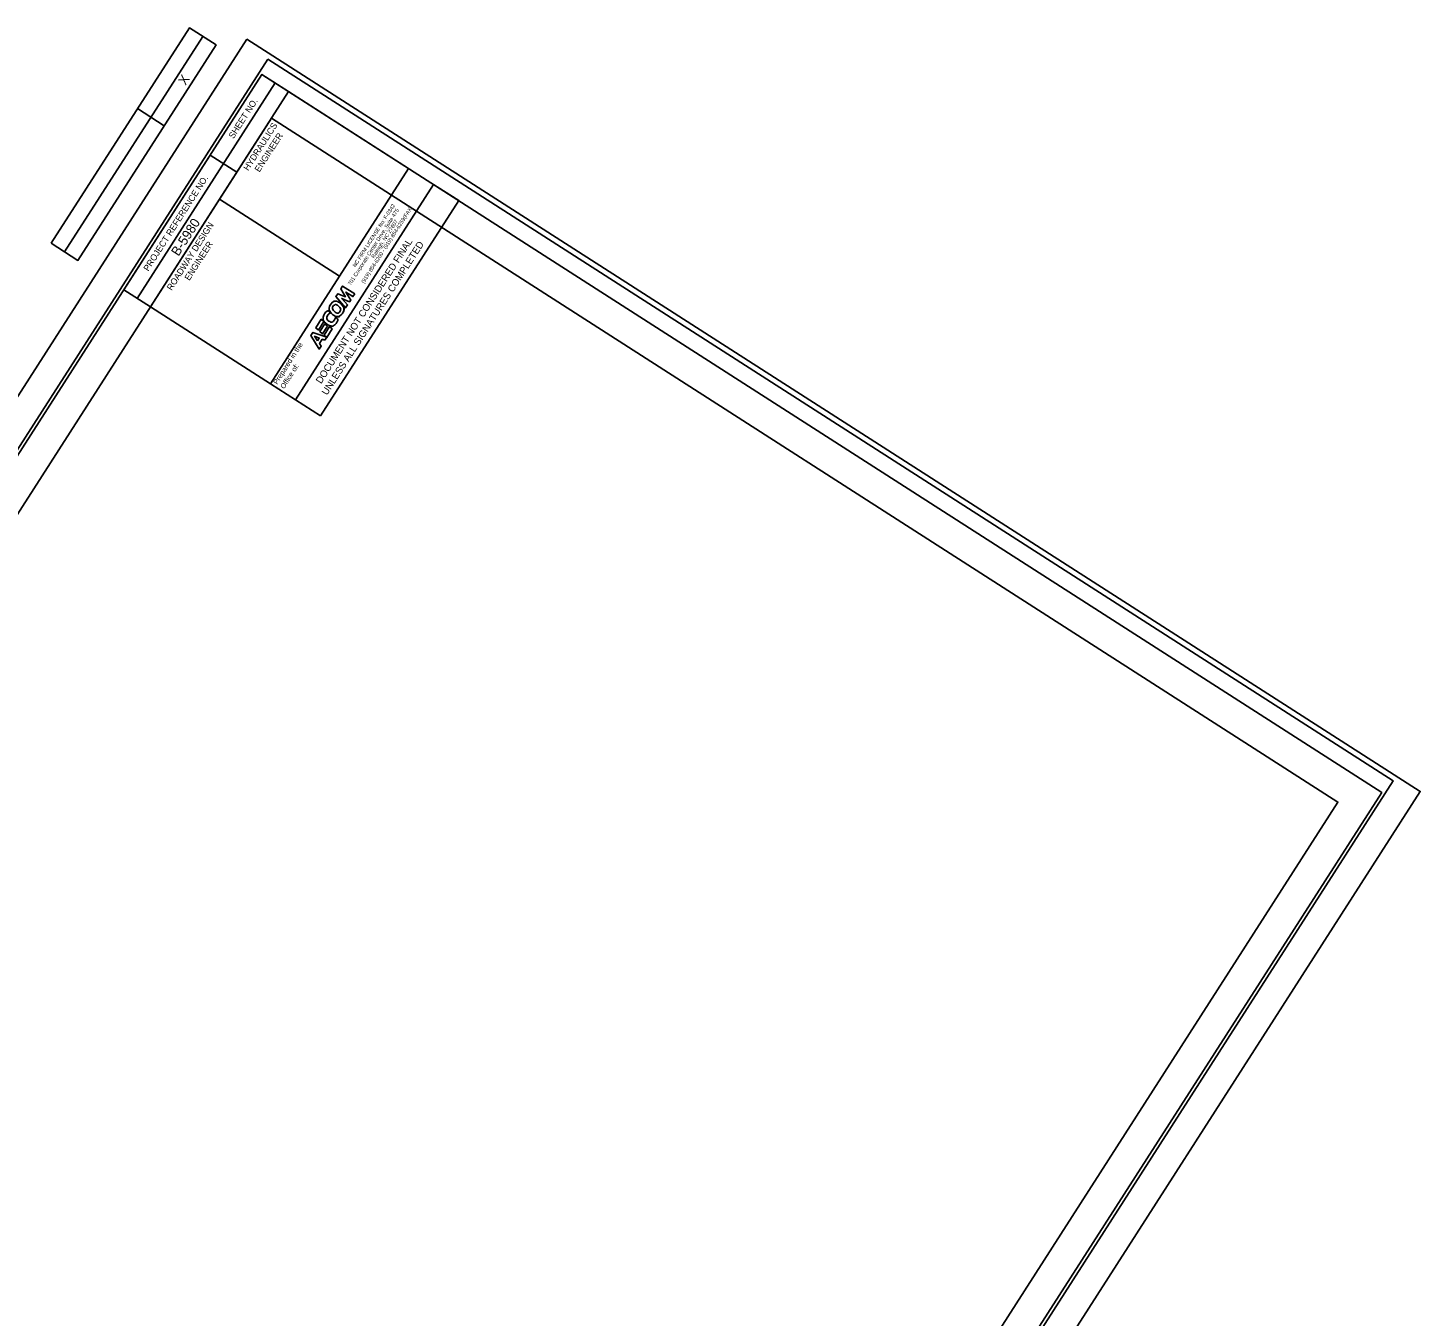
# Model space of a CAD drawing. Extents: x 2346017 to 2347860, y 841329 to 843363.
# Drawn here: x 2346762 to 2347860, y 842346 to 843363 of the extents above; entities that cross this region are included whole.
import ezdxf

# ---------------------------------------------------------------- set-up
doc = ezdxf.new("R2010")
doc.units = 0
for name, color, linetype in [('Default', 7, 'Continuous'), ('Old_Level_49', 7, 'Continuous'), ('Scratch_Level_0', 7, 'Continuous'), ('Sheet Border Standard 30in CELL', 7, 'Continuous'), ('Sheet Data Field CELL', 7, 'Continuous'), ('Sheet Plot Border Inside CELL', 7, 'Continuous'), ('Sheet Plot Border Outside CELL', 7, 'Continuous'), ('Sheet Profile CELL', 7, 'Continuous'), ('Sheet Sticker Exception Certification CELL', 7, 'Continuous')]:
    doc.layers.add(name, color=color, linetype=linetype)

# ---------------------------------------------------------------- blocks, each defined once
blk = doc.blocks.new('block 2')
at = {"layer": 'Default'}
for p, q in [((0.1023, 0.0938), (0.102, 0.0913)), ((0.102, 0.0913), (0.1093, 0.0913)), ((0.1097, 0.0938), (0.1023, 0.0938)), ((0.1093, 0.0913), (0.1097, 0.0938)), ((0.1011, 0.0858), (0.1008, 0.0833)), ((0.1008, 0.0833), (0.1081, 0.0833)), ((0.1085, 0.0858), (0.1011, 0.0858)), ((0.1014, 0.0873), (0.1017, 0.0898)), ((0.1078, 0.0873), (0.1014, 0.0873)), ((0.1017, 0.0898), (0.1082, 0.0898)), ((0.1082, 0.0898), (0.1078, 0.0873)), ((0.1081, 0.0833), (0.1085, 0.0858))]:
    blk.add_line(p, q, dxfattribs=at)
for points in [[(0.1093, 0.0913), (0.102, 0.0913), (0.1023, 0.0938), (0.1097, 0.0938), (0.1093, 0.0913)], [(0.1085, 0.0858), (0.1011, 0.0858), (0.1008, 0.0833), (0.1081, 0.0833), (0.1085, 0.0858)], [(0.1078, 0.0873), (0.1014, 0.0873), (0.1017, 0.0898), (0.1082, 0.0898), (0.1078, 0.0873)]]:
    blk.add_lwpolyline(points, dxfattribs=at)
blk = doc.blocks.new('block 3')
at = {"layer": 'Default'}
blk.add_open_spline([(0.1228, 0.0939), (0.1255, 0.0937), (0.1273, 0.0915), (0.127, 0.0884), (0.1266, 0.0853), (0.1241, 0.083), (0.1213, 0.0832), (0.1185, 0.0834), (0.1168, 0.0856), (0.1171, 0.0887), (0.1174, 0.0918), (0.1199, 0.0941), (0.1228, 0.0939)], degree=3, dxfattribs=at)

msp = doc.modelspace()

# ---------------------------------------------------------------- linework, layer by layer
at = {"layer": 'Old_Level_49'}
for p, q in [((2347006.1, 843153.2), (2347004.7, 843151)), ((2347012.2, 843150.8), (2347006.1, 843153.2)), ((2347009.9, 843159.2), (2347008.6, 843157)), ((2347008.6, 843157), (2347012.2, 843150.8)), ((2347019.6, 843153.2), (2347009.9, 843159.2)), ((2347016.3, 843148.1), (2347012.5, 843154.5)), ((2347012.5, 843154.5), (2347018.1, 843150.9)), ((2347018.1, 843150.9), (2347019.6, 843153.2)), ((2347004.7, 843151), (2347012.3, 843142)), ((2347013.9, 843144.3), (2347009.3, 843149.5)), ((2347009.3, 843149.5), (2347015.5, 843146.9)), ((2347012.3, 843142), (2347013.9, 843144.3)), ((2347015.5, 843146.9), (2347016.3, 843148.1)), ((2346986.5, 843122.7), (2346984.9, 843120.1)), ((2346984.9, 843120.1), (2346991.5, 843109.5)), ((2346997.5, 843118.8), (2346986.5, 843122.7)), ((2346990.2, 843116.1), (2346987.8, 843119.6)), ((2346987.8, 843119.6), (2346987.8, 843119.6)), ((2346987.8, 843119.6), (2346991.5, 843118.2)), ((2346991.5, 843118.2), (2346990.2, 843116.1)), ((2346991.5, 843109.5), (2346993.1, 843111.9)), ((2346991.7, 843113.9), (2346993.9, 843117.3)), ((2346993.1, 843111.9), (2346991.7, 843113.9)), ((2346993.9, 843117.3), (2346996, 843116.5)), ((2346996, 843116.5), (2346997.5, 843118.8))]:
    msp.add_line(p, q, dxfattribs=at)
for points in [[(2347019.6, 843153.2), (2347009.9, 843159.2), (2347008.6, 843157), (2347012.2, 843150.8), (2347006.1, 843153.2), (2347004.7, 843151), (2347012.3, 843142), (2347013.9, 843144.3), (2347009.3, 843149.5), (2347015.5, 843146.9), (2347016.3, 843148.1), (2347012.5, 843154.5), (2347018.1, 843150.9), (2347019.6, 843153.2)], [(2346996, 843116.5), (2346997.5, 843118.8), (2346986.5, 843122.7), (2346984.9, 843120.1), (2346991.5, 843109.5), (2346993.1, 843111.9), (2346991.7, 843113.9), (2346993.9, 843117.3), (2346996, 843116.5)], [(2346990.2, 843116.1), (2346987.8, 843119.6), (2346987.8, 843119.6), (2346991.5, 843118.2), (2346990.2, 843116.1)]]:
    msp.add_lwpolyline(points, dxfattribs=at)
for points in [[(2347008.8, 843136.5), (2347007, 843134.9), (2347004.4, 843135), (2347002.1, 843136.8), (2346999.5, 843138.9), (2346998.8, 843142.6), (2347000.7, 843145)], [(2347000.7, 843145), (2347002.5, 843147.5), (2347005.6, 843147.7), (2347008.1, 843145.7), (2347010.8, 843143.5), (2347011.4, 843139.9), (2347009.6, 843137.4), (2347009.4, 843137.1), (2347009.1, 843136.8), (2347008.8, 843136.5)], [(2347006.9, 843143.2), (2347005.5, 843144.6), (2347003.9, 843144.8), (2347002.9, 843143.8), (2347001.7, 843142.6), (2347002, 843140.7), (2347003.4, 843139.3), (2347004.8, 843137.9), (2347006.5, 843137.7), (2347007.5, 843138.7), (2347008.6, 843139.9), (2347008.4, 843141.8), (2347006.9, 843143.2)], [(2347006.9, 843143.2), (2347005.5, 843144.6), (2347003.9, 843144.8), (2347002.9, 843143.8), (2347001.7, 843142.6), (2347002, 843140.7), (2347003.4, 843139.3), (2347004.8, 843137.9), (2347006.5, 843137.7), (2347007.5, 843138.7), (2347008.6, 843139.9), (2347008.4, 843141.8), (2347006.9, 843143.2)], [(2347004.2, 843134.7), (2347004.1, 843133.9), (2347003.6, 843132.9), (2347003.3, 843132.4), (2347002.3, 843130.9), (2347000.6, 843130.6), (2346999.1, 843131.6), (2346997.6, 843132.7), (2346997.2, 843134.7), (2346998.3, 843136.3), (2346998.8, 843137.1), (2346999.5, 843137.6), (2347000.4, 843137.9), (2347000.4, 843137.9), (2346998.4, 843139.8), (2346998.4, 843139.8), (2346997.2, 843139.2), (2346996.5, 843138.6), (2346995.9, 843137.6), (2346994.1, 843134.9), (2346994.9, 843131.1), (2346997.7, 843129.2), (2347000.5, 843127.3), (2347003.6, 843127.9), (2347005.3, 843130.6), (2347005.6, 843131), (2347006.2, 843132.1), (2347006.3, 843132.9), (2347006.3, 843132.9), (2347004.2, 843134.7), (2347004.2, 843134.7)], [(2347004.2, 843134.7), (2347004.1, 843133.9), (2347003.6, 843132.9), (2347003.3, 843132.4), (2347002.3, 843130.9), (2347000.6, 843130.6), (2346999.1, 843131.6), (2346997.6, 843132.7), (2346997.2, 843134.7), (2346998.3, 843136.3), (2346998.8, 843137.1), (2346999.5, 843137.6), (2347000.4, 843137.9), (2347000.4, 843137.9), (2346998.4, 843139.8), (2346998.4, 843139.8), (2346997.2, 843139.2), (2346996.5, 843138.6), (2346995.9, 843137.6), (2346994.1, 843134.9), (2346994.9, 843131.1), (2346997.7, 843129.2), (2347000.5, 843127.3), (2347003.6, 843127.9), (2347005.3, 843130.6), (2347005.6, 843131), (2347006.2, 843132.1), (2347006.3, 843132.9), (2347006.3, 843132.9), (2347004.2, 843134.7), (2347004.2, 843134.7)]]:
    msp.add_open_spline(points, degree=3, dxfattribs=at)
at = {"layer": 'Scratch_Level_0'}
msp.add_lwpolyline([(2346953.8, 843291.8), (2346163.3, 842059.1), (2347005, 841519.3), (2347795.5, 842752)], close=True, dxfattribs=at)
at = {"layer": 'Sheet Border Standard 30in CELL'}
for p, q in [((2346790.5, 843186.2), (2346899.5, 843356.3)), ((2346801, 843179.5), (2346910.1, 843349.5)), ((2346847.8, 843149.5), (2346956.8, 843319.6)), ((2346858.3, 843142.8), (2346967.3, 843312.8)), ((2346858.3, 843142.8), (2346967.3, 843312.8)), ((2346848.1, 843299.3), (2346869.2, 843285.8)), ((2346905.4, 843262.6), (2346926.4, 843249.1)), ((2346912.8, 843227.8), (2347007.5, 843167.1))]:
    msp.add_line(p, q, dxfattribs=at)
for points in [[(2346780, 843193), (2346889, 843363), (2346910.1, 843349.5), (2346801, 843179.5)], [(2346946.2, 843326.3), (2346128.7, 842051.6), (2347012.6, 841484.8), (2347830.1, 842759.5)], [(2346837.2, 843156.3), (2346946.2, 843326.3), (2346967.3, 843312.8), (2346858.3, 843142.8)], [(2346912.8, 843227.8), (2346967.3, 843312.8), (2347062, 843252.1), (2347007.5, 843167.1)], [(2346858.3, 843142.8), (2346912.8, 843227.8), (2347007.5, 843167.1), (2346953, 843082.1)]]:
    msp.add_lwpolyline(points, close=True, dxfattribs=at)
at = {"layer": 'Sheet Plot Border Inside CELL'}
msp.add_lwpolyline([(2346950.9, 843338.3), (2346042.7, 841922.1), (2346930.8, 841352.5), (2347839, 842768.8)], close=True, dxfattribs=at)
at = {"layer": 'Sheet Plot Border Outside CELL'}
msp.add_lwpolyline([(2346934.4, 843354.2), (2346016.7, 841923.2), (2346942.7, 841329.4), (2347860.4, 842760.4)], close=True, dxfattribs=at)
at = {"layer": 'Sheet Profile CELL'}
msp.add_line((2346953, 843082.1), (2346972.8, 843069.4), dxfattribs=at)
at = {"layer": 'Sheet Sticker Exception Certification CELL'}
for p, q in [((2346972.8, 843069.4), (2347081.8, 843239.4)), ((2347081.8, 843239.4), (2347101.6, 843226.7)), ((2347101.6, 843226.7), (2346992.5, 843056.7)), ((2346992.5, 843056.7), (2346972.8, 843069.4))]:
    msp.add_line(p, q, dxfattribs=at)

# ---------------------------------------------------------------- block references
at = {"layer": 'Old_Level_49', "xscale": 1084.8432715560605, "yscale": 1084.8432715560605, "rotation": 57.32454195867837}
for name in ['block 3', 'block 2']:
    msp.add_blockref(name, (2347014.5, 842977.9), dxfattribs=at)

# ---------------------------------------------------------------- texts
at = {"layer": 'Old_Level_49'}
for s, height, p in [('701 Corporate Center Drive, Suite 475', 3.013, (2347016.3, 843159.4)), ('NC FIRM LICENSE No: F-0342', 3.013, (2347020.1, 843173.8)), ('(919) 854-6200 - (919) 854-6259(FAX)', 3.013, (2347026.9, 843161)), ('Raleigh, NC 27607', 3.013, (2347034.8, 843180.8)), ('Prepared in the ', 4.018, (2346958.3, 843081.2)), ('Office of:', 4.02, (2346963.8, 843077.7))]:
    msp.add_text(s, height=height, rotation=57.3245, dxfattribs=at).set_placement(p)
at = {"layer": 'Sheet Border Standard 30in CELL'}
for s, p in [('SHEET NO.', (2346923.8, 843275.1)), ('HYDRAULICS', (2346935.5, 843249.8)), ('ENGINEER', (2346944.3, 843248.7)), ('PROJECT REFERENCE NO.', (2346856.6, 843170.5)), ('ROADWAY DESIGN', (2346875, 843155.3)), ('ENGINEER', (2346889, 843163.1))]:
    msp.add_text(s, height=5, rotation=57.3281, dxfattribs=at).set_placement(p)
at = {"layer": 'Sheet Data Field CELL'}
for s, p in [('X', (2346886, 843317.2)), ('B-5980', (2346880.4, 843182.3))]:
    msp.add_text(s, height=7.5, rotation=57.3281, dxfattribs=at).set_placement(p)
at = {"layer": 'Sheet Sticker Exception Certification CELL'}
for s, p in [('DOCUMENT NOT CONSIDERED FINAL', (2346993, 843081.7)), ('UNLESS ALL SIGNATURES COMPLETED', (2346997.6, 843072.6))]:
    msp.add_text(s, height=5.5, rotation=57.3281, dxfattribs=at).set_placement(p)

doc.saveas('drawing.dxf')
